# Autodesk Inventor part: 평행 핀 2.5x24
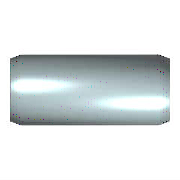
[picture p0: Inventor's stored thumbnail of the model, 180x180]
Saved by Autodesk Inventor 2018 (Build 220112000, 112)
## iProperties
IsCustomPart: 1
Created: 2012-02
Part Number: 평행 핀 2.5x24
Material: 강철, 연강
Description: 평행 핀
Document SubType Name: Modeling
Standard: KS B 1320
Designer: mduedu
Standards Organization: KS
Language: ko-KR
Size Designation: B 2.5 x  24
Categories: <MemberInstance><Categories><Category DisplayName="조임쇠" InternalName="e4da775c-781d-43d5-af7c-5136215cf5a6" Mnemonic="FSTN"><Category DisplayName="핀" InternalNa
Density: 1 g/cm^3
Appearance: 노란색
Author: mduedu
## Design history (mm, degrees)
sketch "스케치"
  geometry: C1 r 1.25 at (0, 0); 1 further point
  constraints: 1 centre point, 1 coincident
  dimensions: "d1" = 2.5 diameter of C1 (= NND)
extrude "본체" new body sketch "스케치" distance "d2" = 24 (= NLG); taper "d3" = 0 deg
chamfer "스케치2" distance "d8" = 0.4 (= PHH); stored, may be unused: angle "d9" = 15 deg (= FAWI), second distance "d12" = 0.4 (= PHH)
node "작업 평면1"
body "Solid1"
chamfer "모따기1" distance "d4" = 0.4 (= PHH); stored, may be unused: angle "d5" = 15 deg (= FAWI), second distance "d11" = 0.4 (= PHH)
other parameters: "NND" = 2.5 [user parameter; used in 1 equation term], "NLG" = 24 [user parameter; used in 1 equation term], "PHH" = 0.4 [user parameter; used in 4 equation terms], "FAWI" = 15 deg [user parameter; used in 2 equation terms], "d13" = 0, "d15" = 0, "d16" = 0, "KAH" = 0.3 [user parameter]
